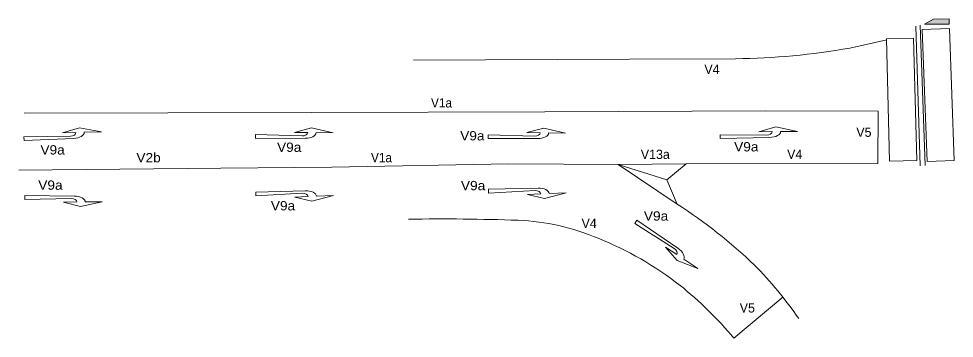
# Model space of a CAD drawing. Extents: x -598770 to -598612, y -1162818 to -1162391.
# Drawn here: x -598764.5 to -598704.2, y -1162655.2 to -1162634.7 of the extents above; entities that cross this region are included whole.
import ezdxf

# ---------------------------------------------------------------- set-up
doc = ezdxf.new("R2010")
doc.units = 0
doc.header["$LTSCALE"] = 0.24
doc.layers.add('47', color=7, linetype='Continuous', lineweight=13)

msp = doc.modelspace()

# ---------------------------------------------------------------- hatches: boundary and pattern name
at = {"layer": '47'}
msp.add_hatch(color=256, dxfattribs=at).paths.add_polyline_path([(-598704.501, -1162634.66), (-598704.492, -1162635.013), (-598706.094, -1162635.01), (-598705.508, -1162634.694)])

# ---------------------------------------------------------------- linework, layer by layer
for p, q in [((-598706.646, -1162635.137), (-598706.37, -1162644.148)), ((-598706.381, -1162635.073), (-598706.05, -1162644.107)), ((-598708.51, -1162636.02), (-598710.91, -1162636.55)), ((-598709.07, -1162640.61), (-598709.1, -1162643.98)), ((-598759.181, -1162641.948), (-598760.28, -1162641.979)), ((-598714.272, -1162641.922), (-598715.372, -1162641.93)), ((-598744.226, -1162642.016), (-598745.326, -1162642.001)), ((-598729.236, -1162642.032), (-598730.336, -1162642.016)), ((-598764.51, -1162644.41), (-598751.48, -1162644.29)), ((-598721.47, -1162644.01), (-598709.1, -1162643.98)), ((-598744.212, -1162646.053), (-598745.311, -1162646.096)), ((-598729.202, -1162645.886), (-598730.302, -1162645.927)), ((-598759.119, -1162646.462), (-598760.219, -1162646.466)), ((-598720.701, -1162650.753), (-598721.62, -1162650.148)), ((-598718.39, -1162655.25), (-598715.23, -1162652.6))]:
    msp.add_line(p, q, dxfattribs=at)
for points in [[(-598704.501, -1162634.66), (-598704.492, -1162635.013), (-598706.094, -1162635.01), (-598705.508, -1162634.694)], [(-598706.234, -1162635.348), (-598705.923, -1162643.855), (-598704.17, -1162643.791), (-598704.481, -1162635.284)], [(-598708.545, -1162635.955), (-598706.79, -1162635.909), (-598706.584, -1162643.8), (-598708.339, -1162643.846)], [(-598725.85, -1162644.05), (-598722.71, -1162645.05), (-598721.47, -1162644.01)], [(-598725.85, -1162644.05), (-598722.04, -1162646.61), (-598722.71, -1162645.05)]]:
    msp.add_lwpolyline(points, close=True, dxfattribs=at)
for points in [[(-598718.28, -1162637.24), (-598725.11, -1162637.27), (-598739.04, -1162637.33)], [(-598709.07, -1162640.61), (-598716.32, -1162640.6), (-598730.57, -1162640.66), (-598745.62, -1162640.7), (-598764.16, -1162640.74)], [(-598760.82, -1162641.995), (-598761.68, -1162642.019), (-598760.589, -1162641.688), (-598759.181, -1162641.948)], [(-598745.866, -1162641.994), (-598746.726, -1162641.983), (-598745.622, -1162641.697), (-598744.226, -1162642.016)], [(-598730.876, -1162642.008), (-598731.736, -1162641.996), (-598730.632, -1162641.712), (-598729.236, -1162642.032)], [(-598715.912, -1162641.934), (-598716.772, -1162641.941), (-598715.675, -1162641.633), (-598714.272, -1162641.922)], [(-598760.969, -1162642.371), (-598764.166, -1162642.515), (-598764.174, -1162642.265), (-598761.173, -1162642.23)], [(-598746.031, -1162642.364), (-598749.232, -1162642.375), (-598749.228, -1162642.125), (-598746.229, -1162642.214)], [(-598731.041, -1162642.378), (-598734.242, -1162642.385), (-598734.238, -1162642.135), (-598731.239, -1162642.228)], [(-598716.07, -1162642.308), (-598719.269, -1162642.385), (-598719.271, -1162642.135), (-598716.271, -1162642.162)], [(-598725.85, -1162644.05), (-598732.91, -1162644.02), (-598744.32, -1162644.23), (-598751.48, -1162644.29)], [(-598731.015, -1162645.581), (-598734.215, -1162645.645), (-598734.205, -1162645.895), (-598731.209, -1162645.735)], [(-598760.92, -1162646.097), (-598764.12, -1162646.055), (-598764.12, -1162646.305), (-598761.12, -1162646.244)], [(-598746.025, -1162645.752), (-598749.225, -1162645.825), (-598749.215, -1162646.075), (-598746.219, -1162645.907)], [(-598745.851, -1162646.117), (-598746.71, -1162646.151), (-598745.599, -1162646.408), (-598744.212, -1162646.053)], [(-598730.841, -1162645.946), (-598731.701, -1162645.978), (-598730.59, -1162646.237), (-598729.202, -1162645.886)], [(-598760.759, -1162646.468), (-598761.619, -1162646.471), (-598760.518, -1162646.767), (-598759.119, -1162646.462)], [(-598721.999, -1162649.452), (-598724.641, -1162647.646), (-598724.779, -1162647.854), (-598722.247, -1162649.464)], [(-598722.07, -1162649.85), (-598722.788, -1162649.377), (-598722.035, -1162650.233), (-598720.701, -1162650.753)]]:
    msp.add_lwpolyline(points, dxfattribs=at)
for centre, radius, start, end in [((-598718.762, -1162592.3861), 44.8564, 270.61573, 280.08147), ((-598739.3142, -1162673.6786), 32.1108, 46.12853, 57.45547), ((-598737.1169, -1162777.0828), 129.5224, 87.86871, 90.99675), ((-598732.8052, -1162661.9536), 14.3125, 66.68303, 87.97734), ((-598735.2581, -1162669.0718), 21.8276, 52.13414, 68.16597), ((-598736.4261, -1162669.4946), 27.1054, 34.9165, 44.39998), ((-598736.3816, -1162670.0876), 23.3207, 39.51234, 51.48698)]:
    msp.add_arc(centre, radius, start, end, dxfattribs=at)
for centre, major_axis, ratio, start_param, end_param in [((-598760.9801, -1162641.999), (0.6997, 0.0199), 0.531429, 4.712389, 6.2831853), ((-598716.2726, -1162641.937), (0.36, 0.0027), 0.625, 4.712389, 6.2831853), ((-598716.0726, -1162641.9354), (0.7, 0.0053), 0.531429, 4.712389, 6.2831853), ((-598761.18, -1162642.0047), (0.3599, 0.0102), 0.625, 4.712389, 6.2831853), ((-598746.2266, -1162641.9892), (0.36, -0.0047), 0.625, 4.712389, 6.2831853), ((-598746.0266, -1162641.9919), (0.6999, -0.0092), 0.531429, 4.712389, 6.2831853), ((-598731.2362, -1162642.003), (0.36, -0.0052), 0.625, 4.712389, 6.2831853), ((-598731.0363, -1162642.0058), (0.6999, -0.0101), 0.531429, 4.712389, 6.2831853), ((-598731.001, -1162645.9524), (-0.6995, -0.0257), 0.531429, 3.1415927, 4.712389), ((-598760.9188, -1162646.4686), (0.7, 0.0025), 0.531429, 0, 1.5707963), ((-598746.2104, -1162646.1316), (0.3597, 0.0142), 0.625, 0, 1.5707963), ((-598746.0105, -1162646.1237), (0.6995, 0.0276), 0.531429, 0, 1.5707963), ((-598731.2009, -1162645.9597), (-0.3598, -0.0132), 0.625, 3.1415927, 4.712389), ((-598761.1188, -1162646.4693), (0.36, 0.0013), 0.625, 0, 1.5707963), ((-598722.3708, -1162649.6524), (-0.3005, 0.1982), 0.625, 3.1415927, 4.712389), ((-598722.2039, -1162649.7625), (-0.5843, 0.3854), 0.531429, 3.1415927, 4.712389)]:
    msp.add_ellipse(centre, major_axis=major_axis, ratio=ratio, start_param=start_param, end_param=end_param, dxfattribs=at)

# ---------------------------------------------------------------- texts
for s, p in [('V4', (-598720.29, -1162638.22)), ('V5', (-598710.49, -1162642.27)), ('V13a', (-598724.39, -1162643.7)), ('V4', (-598714.95, -1162643.69)), ('V4', (-598728.21, -1162648.14)), ('V5', (-598718.01, -1162653.59))]:
    msp.add_text(s, height=0.6, dxfattribs=at).set_placement(p)
for s, width, p in [('V1a', 0.95, (-598737.92, -1162640.38)), ('V9a', 1.1, (-598736.04, -1162642.5)), ('V9a', 1.1, (-598763.11, -1162643.41)), ('V9a', 1.1, (-598747.85, -1162643.24)), ('V9a', 1.1, (-598718.37, -1162643.21)), ('V2b', 1.1, (-598756.92, -1162643.91)), ('V1a', 0.95, (-598741.79, -1162643.91)), ('V9a', 1.1, (-598763.25, -1162645.68)), ('V9a', 1.1, (-598735.99, -1162645.71)), ('V9a', 1.1, (-598748.25, -1162647.01)), ('V9a', 1.1, (-598724.19, -1162647.67))]:
    msp.add_text(s, height=0.6, dxfattribs=dict(at, width=width)).set_placement(p)

doc.saveas('drawing.dxf')
